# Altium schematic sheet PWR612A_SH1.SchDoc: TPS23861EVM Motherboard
size 558 x 431 mm; Engineer: E. Wright; Revision: A; Name: E. Wright
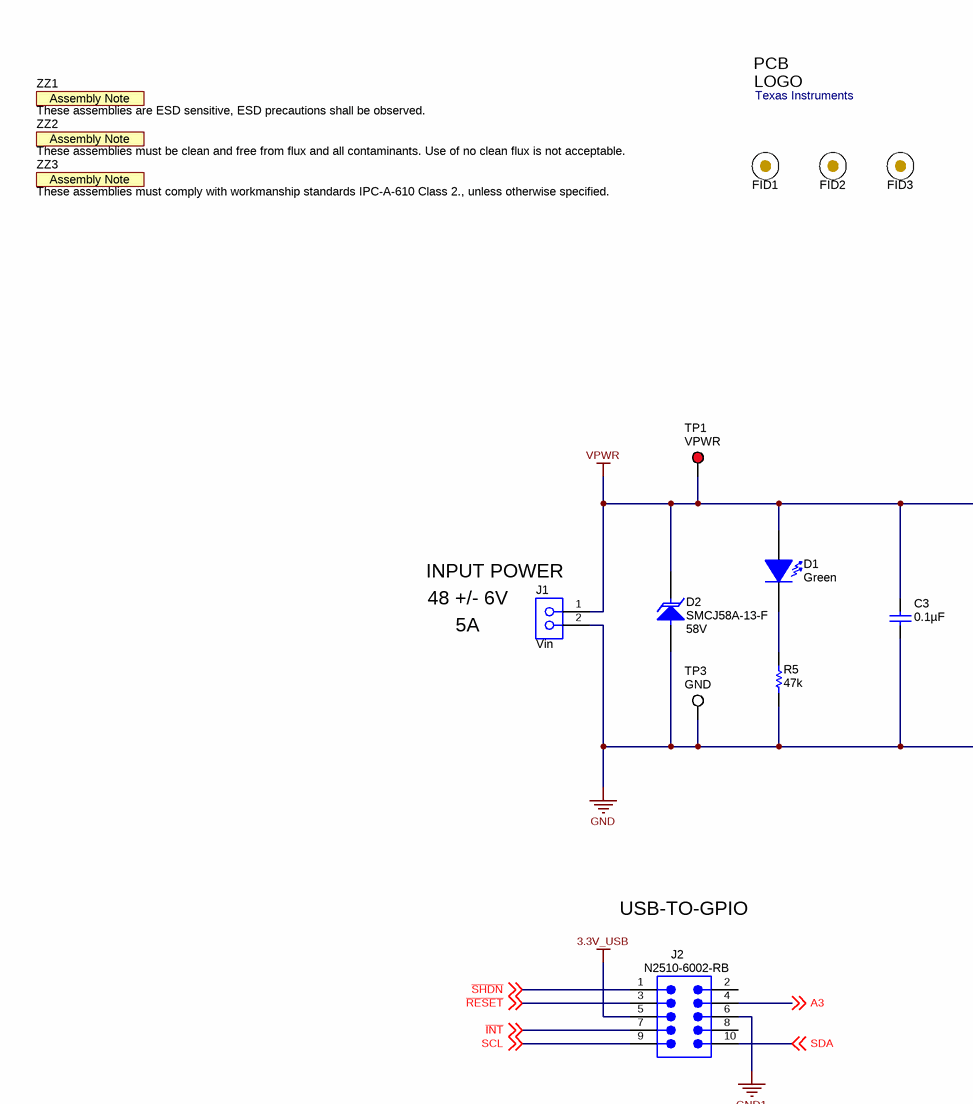
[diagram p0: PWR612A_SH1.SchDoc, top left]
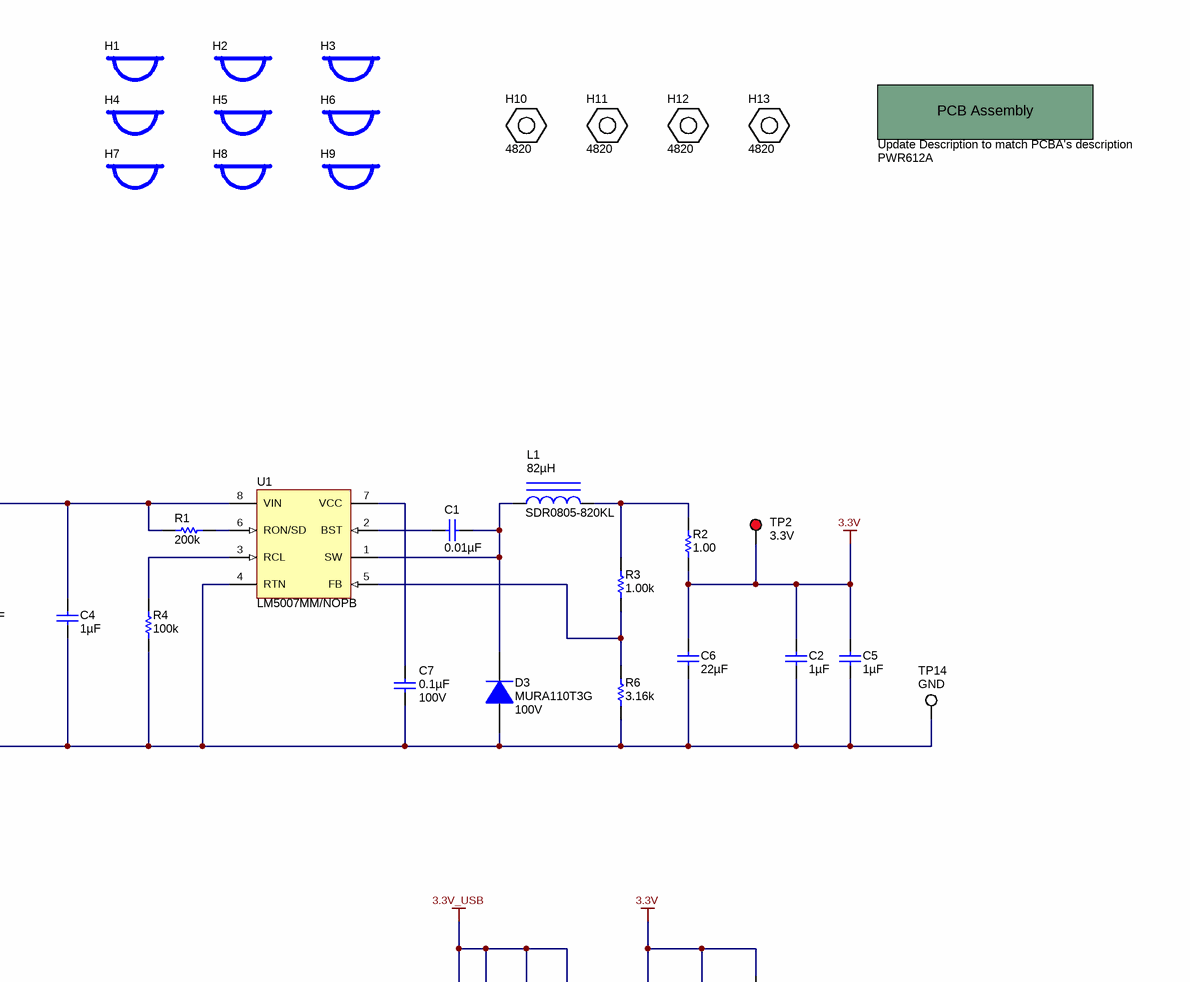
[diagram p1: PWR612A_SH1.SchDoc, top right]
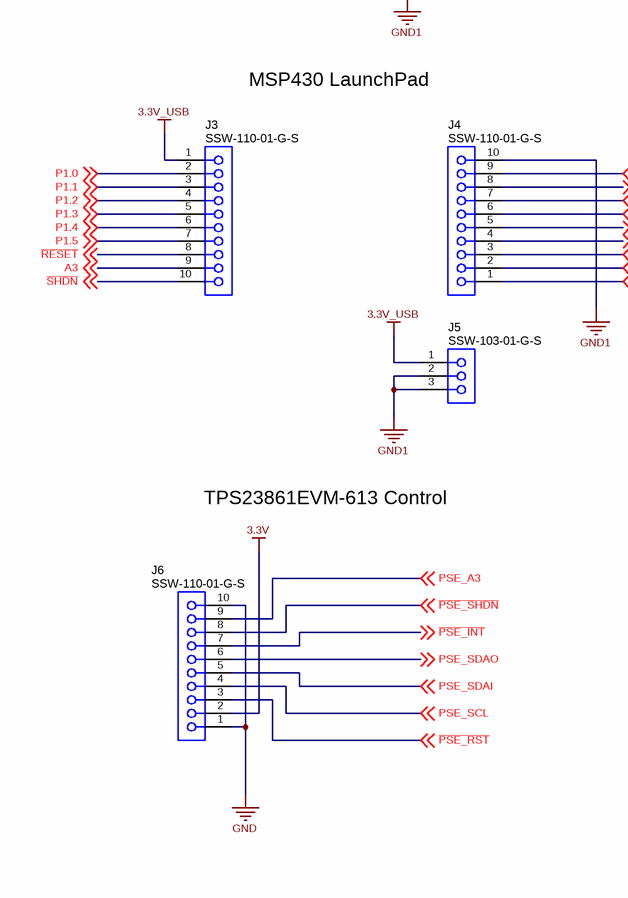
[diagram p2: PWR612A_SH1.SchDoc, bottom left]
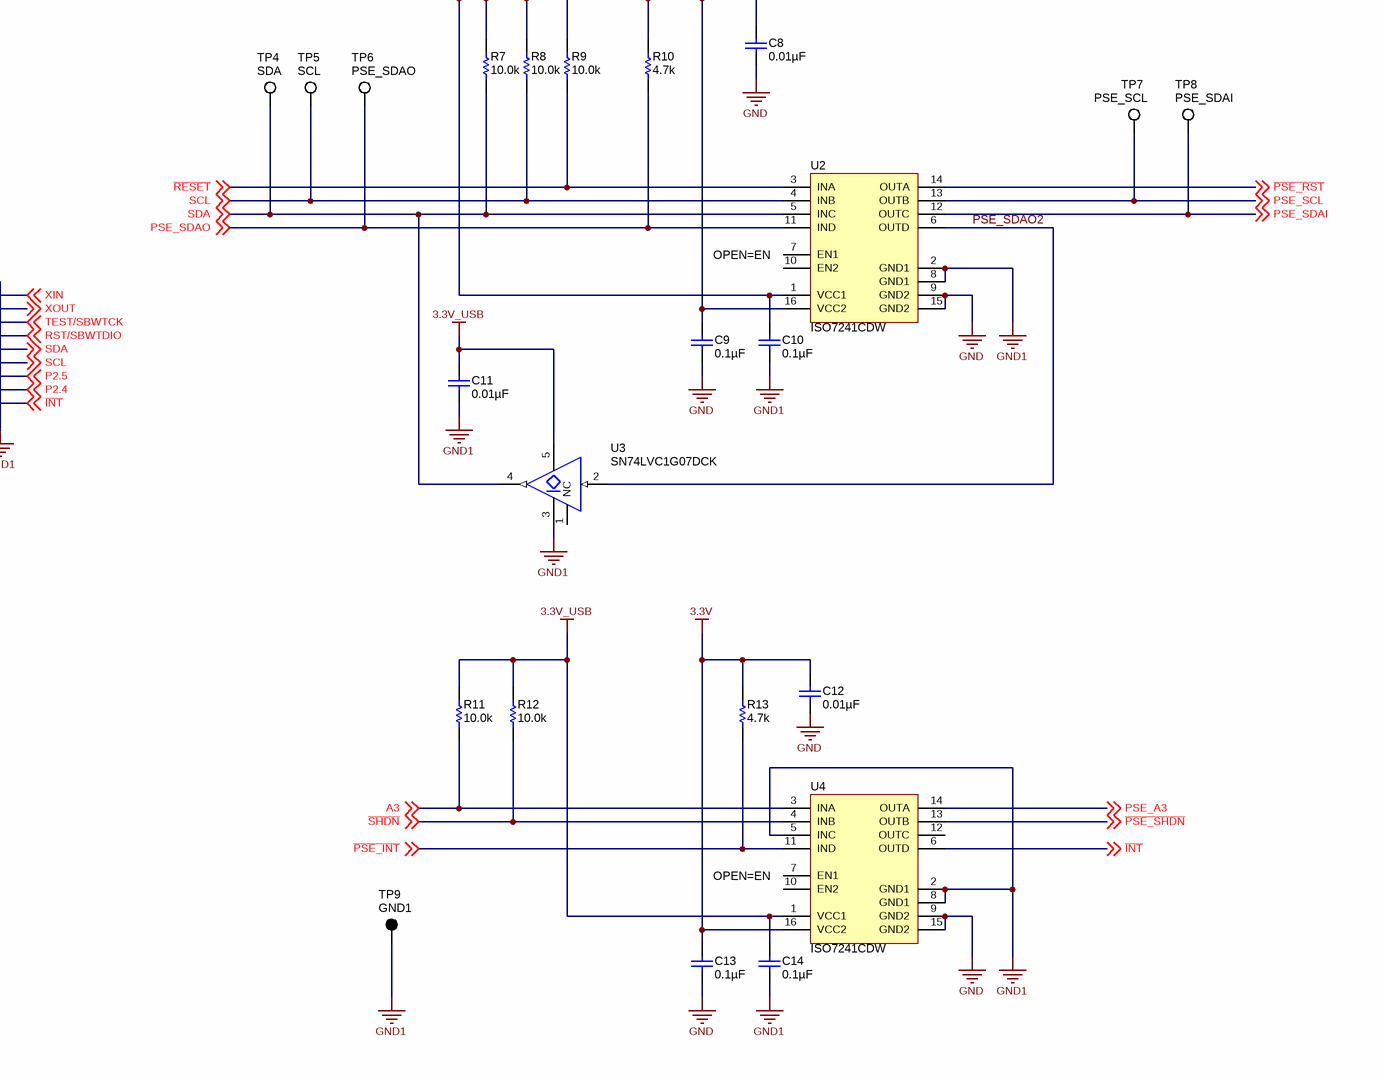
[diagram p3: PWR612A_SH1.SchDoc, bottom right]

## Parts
!PCBA?  Update Description to match PCBA's description  PartNumber: PWR612A  (mechanical)
C1  ValueDisplayed: 0.01µF  [0603]  (hidden comment: 06031C103KAT2A)
C2  ValueDisplayed: 1µF  [0805]  (hidden comment: 0805ZC105KAT2A)
C3  ValueDisplayed: 0.1µF  [0805_HV]  (hidden comment: C2012X7R2A104K)
C4  ValueDisplayed: 1µF  [1206]  (hidden comment: GRM31CR72A105KA01L)
C5  ValueDisplayed: 1µF  [0805]  (hidden comment: 0805ZC105KAT2A)
C6  ValueDisplayed: 22µF  [1206]  (hidden comment: GRM31CR71A226KE15L)
C7  ValueDisplayed: 0.1µF  Value2: 100V  [0805_HV]  (hidden comment: C2012X7R2A104K)
C8  ValueDisplayed: 0.01µF  [0603]  (hidden comment: 06031C103KAT2A)
C9  ValueDisplayed: 0.1µF  [0603]  (hidden comment: 06035C104KAT2A)
C10  ValueDisplayed: 0.1µF  [0603]  (hidden comment: 06035C104KAT2A)
C11  ValueDisplayed: 0.01µF  [0603]  (hidden comment: 06031C103KAT2A)
C12  ValueDisplayed: 0.01µF  [0603]  (hidden comment: 06031C103KAT2A)
C13  ValueDisplayed: 0.1µF  [0603]  (hidden comment: 06035C104KAT2A)
C14  ValueDisplayed: 0.1µF  [0603]  (hidden comment: 06035C104KAT2A)
D1  value Green  [LED_PowerTOPLED_CB_lens]  (hidden comment: LT E63C-CADB-35-L-Z)
D2  SMCJ58A-13-F  value 58V  [SMC]
D3  MURA110T3G  value 100V  [SMA]
FID1  Fiducial  [Fiducial10-20]  (value not drawn)  (no BOM)
FID2  Fiducial  [Fiducial10-20]  (value not drawn)  (no BOM)
FID3  Fiducial  [Fiducial10-20]  (value not drawn)  (no BOM)
H1  SJ61A1  [Bumpon_SJ61A1]  (value not drawn)
H2  SJ61A1  [Bumpon_SJ61A1]  (value not drawn)
H3  SJ61A1  [Bumpon_SJ61A1]  (value not drawn)
H4  SJ61A1  [Bumpon_SJ61A1]  (value not drawn)
H5  SJ61A1  [Bumpon_SJ61A1]  (value not drawn)
H6  SJ61A1  [Bumpon_SJ61A1]  (value not drawn)
H7  SJ61A1  [Bumpon_SJ61A1]  (value not drawn)
H8  SJ61A1  [Bumpon_SJ61A1]  (value not drawn)
H9  SJ61A1  [Bumpon_SJ61A1]  (value not drawn)
H10  4820  [KEYSTONE_4820]
H11  4820  [KEYSTONE_4820]
H12  4820  [KEYSTONE_4820]
H13  4820  [KEYSTONE_4820]
J1  Vin  [CONN_ED120-2DS]
J2  N2510-6002-RB  [CONN_2510-6002]
J3  SSW-110-01-G-S  [CONN_SSW-110-23-F-S]
J4  SSW-110-01-G-S  [CONN_SSW-110-23-F-S]
J5  SSW-103-01-G-S  [CONN_SSW-103-01-G-S]
J6  SSW-110-01-G-S  [CONN_SSW-110-23-F-S]
L1  SDR0805-820KL  ValueDisplayed: 82µH  [SDR0805]
Logo1  Texas Instruments  [TI_Stacked_Overlay_Medium]  (no BOM)
R1  value 200k  [0603]  (hidden comment: CRCW0603200KFKEA)
R2  value 1.00  [1206]  (hidden comment: CRCW12061R00FKEA)
R3  value 1.00k  [0603]  (hidden comment: CRCW06031K00FKEA)
R4  value 100k  [0603]  (hidden comment: CRCW0603100KFKEA)
R5  value 47k  [0603]  (hidden comment: CRCW060347K0JNEA)
R6  value 3.16k  [0603]  (hidden comment: CRCW06033K16FKEA)
R7  value 10.0k  [0603]  (hidden comment: CRCW060310K0FKEA)
R8  value 10.0k  [0603]  (hidden comment: CRCW060310K0FKEA)
R9  value 10.0k  [0603]  (hidden comment: CRCW060310K0FKEA)
R10  value 4.7k  [0603]  (hidden comment: CRCW06034K70JNEA)
R11  value 10.0k  [0603]  (hidden comment: CRCW060310K0FKEA)
R12  value 10.0k  [0603]  (hidden comment: CRCW060310K0FKEA)
R13  value 4.7k  [0603]  (hidden comment: CRCW06034K70JNEA)
TP1  VPWR  [Keystone5010]
TP2  3.3V  [Keystone5010]
TP3  GND  [Testpoint_Keystone_Compact]
TP4  SDA  [Keystone5012]
TP5  SCL  [Keystone5012]
TP6  PSE_SDAO  [Keystone5012]
TP7  PSE_SCL  [Keystone5012]
TP8  PSE_SDAI  [Keystone5012]
TP9  GND1  [Keystone5011]
TP14  GND  [Testpoint_Keystone_Compact]
U1  LM5007MM/NOPB  [MUA08A_N]
U2  ISO7241CDW  [DW0016A_N]
U3  SN74LVC1G07DCK  [DCK0005A_N]
U4  ISO7241CDW  [DW0016A_N]
ZZ1  These assemblies are ESD sensitive, ESD precautions shall be observed.  [AssemblyNote]  (no BOM)
ZZ2  These assemblies must be clean and free from flux and all contaminants. Use of no clean flux is not acceptable.  [AssemblyNote]  (no BOM)
ZZ3  These assemblies must comply with workmanship standards IPC-A-610 Class 2., unless otherwise specified.  [AssemblyNote]  (no BOM)

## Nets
3.3V: C2.1 C5.1 C6.1 C8.2 C9.1 C12.2 C13.1 J6.2 R2.2 R10.2 R13.2 TP2.1 U2.16(VCC2) U4.16(VCC2)
3.3V_USB: C10.1 C11.2 C14.1 J2.5 J3.1 J5.1 R7.2 R8.2 R9.2 R11.2 R12.2 U2.1(VCC1) U3.5(VCC) U4.1(VCC1)
GND: C2.2 C3.2 C4.2 C5.2 C6.2 C7.2 C8.1 C9.2 C12.1 C13.2 D2.2(A) D3.2(A) J1.2 J6.1 J6.10 R4.1 R5.1 R6.1 TP3.1 TP14.1 U1.4(RTN) U2.9(GND2) U2.15(GND2) U4.9(GND2) U4.15(GND2)
GND1: C10.2 C11.1 C14.2 J2.6 J4.10 J5.2 J5.3 TP9.1 U2.2(GND1) U2.8(GND1) U3.3(GND) U4.2(GND1) U4.5(INC) U4.8(GND1)
VPWR: C3.1 C4.1 D1.4(A) D2.1(K) J1.1 R1.1 TP1.1 U1.8(VIN)
~{INT}: J2.7 J4.1 U4.6(OUTD) ; off-sheet ~{INT}
~{PSE_INT}: J6.7 R13.1 U4.11(IND) ; off-sheet ~{PSE_INT}
~{PSE_RST}: J6.3 U2.14(OUTA) ; off-sheet ~{PSE_RST}
~{PSE_SHDN}: J6.8 U4.13(OUTB) ; off-sheet ~{PSE_SHDN}
~{RESET}: J2.3 J3.8 R9.1 U2.3(INA) ; off-sheet ~{RESET}
~{SHDN}: J2.1 J3.10 R12.1 U4.4(INB) ; off-sheet ~{SHDN}
A3: J2.4 J3.9 R11.1 U4.3(INA) ; off-sheet A3
P1.0: J3.2 ; off-sheet P1.0
P1.1: J3.3 ; off-sheet P1.1
P1.2: J3.4 ; off-sheet P1.2
P1.3: J3.5 ; off-sheet P1.3
P1.4: J3.6 ; off-sheet P1.4
P1.5: J3.7 ; off-sheet P1.5
P2.4: J4.2 ; off-sheet P2.4
P2.5: J4.3 ; off-sheet P2.5
PSE_A3: J6.9 U4.14(OUTA) ; off-sheet PSE_A3
PSE_SCL: J6.4 TP7.1 U2.13(OUTB) ; off-sheet PSE_SCL
PSE_SDAI: J6.5 TP8.1 U2.12(OUTC) ; off-sheet PSE_SDAI
PSE_SDAO: J6.6 R10.1 TP6.1 U2.11(IND) ; off-sheet PSE_SDAO
PSE_SDAO2: U2.6(OUTD) U3.2(A)
RST/SBWTDIO: J4.6 ; off-sheet RST/SBWTDIO
SCL: J2.9 J4.4 R8.1 TP5.1 U2.4(INB) ; off-sheet SCL
SDA: J2.10 J4.5 R7.1 TP4.1 U2.5(INC) U3.4(Y) ; off-sheet SDA
TEST/SBWTCK: J4.7 ; off-sheet TEST/SBWTCK
XIN: J4.9 ; off-sheet XIN
XOUT: J4.8 ; off-sheet XOUT
NetC1_1: C1.1 U1.2(BST)
NetC1_2: C1.2 D3.1(K) L1.1 U1.1(SW)
NetC7_1: C7.1 U1.7(VCC)
NetD1_2: D1.2(K) R5.2
NetL1_2: L1.2 R2.1 R3.2
NetR1_2: R1.2 U1.6(RON/SD)
NetR3_1: R3.1 R6.2 U1.5(FB)
NetR4_2: R4.2 U1.3(RCL)

Not connected (* = marked no-connect by the designer): J2 2 8; U2 7(EN1) 10(EN2); U3 1(NC); U4 7(EN1) 10(EN2) 12(OUTC)

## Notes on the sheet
- (near J1) 48 +/- 6V
- (near J1) INPUT POWER
- 5A
- USB-TO-GPIO
- MSP430 LaunchPad
- (near U2) OPEN=EN
- TPS23861EVM-613 Control
- (near U4) OPEN=EN

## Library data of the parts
!PCBA? = PCBA: Manufacturer: Any; SymbolCreator: a0412235; U/M: EA
C1 C8 C11 C12 = 06031C103KAT2A: CAP, CERM, 0.01uF, 100V, +/-10%, X7R, 0603; Manufacturer: AVX; Polarized: N; CompType: Capacitor; U/M: EA; Cap_F: 0.00000001; Tolerance_%: 10; ESR_Ohm: 0.098; Value1: 0.098 ohm; VDC_V: 100; TaMin_C: -55; TaMax_C: 125
C2 C5 = 0805ZC105KAT2A: CAP, CERM, 1uF, 10V, +/-10%, X7R, 0805; Manufacturer: AVX; Polarized: N; CompType: Capacitor; U/M: EA; Cap_F: 0.000001; Tolerance_%: 10; ESR_Ohm: 0.008; Value1: 0.008 ohm; TaMin_C: -55; TaMax_C: 125
C3 C7 = C2012X7R2A104K: CAP, CERM, 0.1uF, 100V, +/-10%, X7R, 0805; Manufacturer: TDK; Polarized: N; CompType: Capacitor; U/M: EA; Cap_F: 0.0000001; Tolerance_%: 10; ESR_Ohm: 0.0158; Value1: 0.0158 ohm; VDC_V: 100; TaMin_C: -55; TaMax_C: 125; Cap_Case: 0805
C4 = GRM31CR72A105KA01L: CAP, CERM, 1uF, 100V, +/-10%, X7R, 1206; Manufacturer: MuRata; Polarized: N; CompType: Capacitor; U/M: EA; Cap_F: 0.000001; Tolerance_%: 10; Value1: Unknown; VDC_V: 100; TaMin_C: -55; TaMax_C: 125; Cap_Case: 2220
C6 = GRM31CR71A226KE15L: CAP, CERM, 22uF, 10V, +/-10%, X7R, 1206; Manufacturer: MuRata; Polarized: N; CompType: Capacitor; U/M: EA; Cap_F: 0.000022; Tolerance_%: 10; Value1: Unknown; TaMin_C: -55; TaMax_C: 125
C9 C10 C13 C14 = 06035C104KAT2A: CAP, CERM, 0.1uF, 50V, +/-10%, X7R, 0603; Manufacturer: AVX; Polarized: N; CompType: Capacitor; U/M: EA; Cap_F: 0.0000001; Tolerance_%: 10; Value1: Unknown; VDC_V: 50; TaMin_C: -55; TaMax_C: 125
D1 = LT E63C-CADB-35-L-Z: LED, Green, SMD; Manufacturer: OSRAM; Type: InGaN; Vf_V: 3.8; Value2: 3.8V; Io_A: 0.03; Vr_V: 5; RJC_CperW: 180; Tjmax_C: 125; Power_TotalModule: 0.114; Value1: 0.114W; LambdaP: 520; LambdaD: 525; NumParallelLEDs: 1; LuminousFlux_PhiV: 1.482; Angle: 20; FamilyName: Power TOPLED&#174;; U/M: EA
D2 = SMBJ58A-13-F: Diode, TVS, Uni, 58V, 600W, SMB; Manufacturer: Diodes Inc.; U/M: EA; Power_W: 5; Vr_V: 58; Value1: 5W
D3 = MURA120T3G: Diode, Ultrafast, 100V, 1A, SMA; Manufacturer: ON Semiconductor; U/M: EA; Vf_V: 0.0875; Value2: 0.0875V; Io_A: 1; Vr_V: 100; TJmax_C: 175
FID1-FID3 = Fiducial: Fiducial mark.  There is nothing to buy or mount.; SymbolCreator: codlsc
H1-H9 = SJ61A1: Bumpon, Cylindrical, 0.312 X 0.200, Black; Manufacturer: 3M; SymbolCreator: a0412235
H10-H13 = 4820: Standoff, Hex, 1"L #6-32 Nylon, M-F; Manufacturer: Keystone; SymbolCreator: a0412235
J1 = ED120/2DS: TERMINAL BLOCK 5.08MM VERT 2POS; Manufacturer: On-Shore Technology, Inc.; U/M: EA
J2 = N2510-6002-RB: Header (shrouded), 100mil, 5x2, High-Temperature, Gold, TH; Manufacturer: 3M; SymbolCreator: a0412235; CompType: Connector; U/M: EA
J3 J4 J6 = SSW-110-23-F-S: Connector, Receptacle, 100mil, 10x1, Gold plated, TH; Manufacturer: Samtec, Inc.; SymbolCreator: a0411947; U/M: EA
J5 = SSW-103-01-G-S: Receptacle 100mil 3x1, Gold, TH; Manufacturer: Samtec, Inc.; SymbolCreator: a0412235; U/M: EA
L1 = SDR0805-820KL: Inductor, Drum Core, Ferrite, 82uH, 0.78A, 0.37 ohm, SMD; Manufacturer: Bourns; Alternate Manufacturer: Wurth Elektronik; Alternate PartNumber: 744787820; Ind_H: 82.0E-6; Imax_A: 0.78; Irms: 0.78A @ 40C rise; Isat: 1.2A @ 10% inductance drop; DCR_ohm: 0.37; U/M: EA
Logo1 = TI_Logo: Texas Instrument Corporate Signature; SymbolCreator: codlsc
R1 = CRCW0603200KFKEA: RES, 200k ohm, 1%, 0.1W, 0603; Manufacturer: Vishay-Dale; CompType: Resistor; Res_ohm: 200000; Tolerance_%: 1; Power_W: 0.1; VDC_V: 75; TempCo: 100 ppm/C; EIA_Code: E96; U/M: EA
R2 = CRCW12061R00FKEA: RES, 1.00 ohm, 1%, 0.25W, 1206; Manufacturer: Vishay-Dale; CompType: Resistor; Res_ohm: 1; Value_Code: 1R00; Power_W: 0.25; VDC_V: 200; TempCo: 100 ppm/C; EIA_Code: E96; U/M: EA
R3 = CRCW06031K00FKEA: RES, 1.00k ohm, 1%, 0.1W, 0603; Manufacturer: Vishay-Dale; CompType: Resistor; Res_ohm: 1000; Value_Code: 1k00; Tolerance_%: 1; Power_W: 0.1; VDC_V: 75; TempCo: 100 ppm/C; EIA_Code: E96; U/M: EA
R4 = CRCW0603100KFKEA: RES, 100k ohm, 1%, 0.1W, 0603; Manufacturer: Vishay-Dale; CompType: Resistor; Res_ohm: 100000; Tolerance_%: 1; Power_W: 0.1; VDC_V: 75; TempCo: 100 ppm/C; EIA_Code: E96; U/M: EA
R5 = CRCW060347K0JNEA: RES, 47k ohm, 5%, 0.1W, 0603; Manufacturer: Vishay-Dale; CompType: Resistor; Res_ohm: 47000; Value_Code: 47k0; Tolerance_%: 5; Power_W: 0.1; VDC_V: 75; TempCo: 200 ppm/C; EIA_Code: E24; U/M: EA
R6 = CRCW06033K16FKEA: RES, 3.16k ohm, 1%, 0.1W, 0603; Manufacturer: Vishay-Dale; CompType: Resistor; Res_ohm: 3160; Value_Code: 3k16; Tolerance_%: 1; Power_W: 0.1; VDC_V: 75; TempCo: 100 ppm/C; EIA_Code: E96; U/M: EA
R7-R9 R11 R12 = CRCW060310K0FKEA: RES, 10.0k ohm, 1%, 0.1W, 0603; Manufacturer: Vishay-Dale; CompType: Resistor; Res_ohm: 10000; Value_Code: 10k0; Tolerance_%: 1; Power_W: 0.1; VDC_V: 75; TempCo: 100 ppm/C; EIA_Code: E96; U/M: EA
R10 R13 = CRCW06034K70JNEA: RES, 4.7k ohm, 5%, 0.1W, 0603; Manufacturer: Vishay-Dale; CompType: Resistor; Res_ohm: 4700; Value_Code: 4k70; Tolerance_%: 5; Power_W: 0.1; VDC_V: 75; TempCo: 200 ppm/C; EIA_Code: E24; U/M: EA
TP1 TP2 = 5010: Test Point, Multipurpose, Red, TH; Manufacturer: Keystone; CompType: Test Point Loop; U/M: EA
TP3 TP14 = 5016: Test Point, Compact, SMT; Manufacturer: Keystone; CompType: Test Point Loop; U/M: EA
TP4-TP8 = 5012: Test Point, Multipurpose, White, TH; Manufacturer: Keystone; CompType: Test Point Loop; U/M: EA
TP9 = 5011: Test Point, Multipurpose, Black, TH; Manufacturer: Keystone; CompType: Test Point Loop; U/M: EA
U1 = LM5007MM/NOPB: High Voltage (80V) Step Down Switching Regulator, 8-pin MSOP, Pb-Free; Manufacturer: National Semiconductor; PackageTopMarking: ZXTT*S81B; PowerWise: N; CompType: Switcher
U2 U4 = ISO7241CDW: 25 Mbps Quad Channels, 3 / 1, Digital Isolator, 3.3 V / 5 V, -40 to +125 degC, 16-pin SOIC (DW), Green (RoHS & no Sb/Br); Manufacturer: Texas Instruments; Alternate Manufacturer: None; Alternate PartNumber: Equivalent; Datarate(Mbps): 25; Eco-Plan: TBD; Input Noise Filter: Yes; Insulation Rating(VRMS): 2500; Prop Delay(Max)(ns): 42; Rating: Catalog; Supply Voltage(s)(V): 3.3, 5; TTL/CMOS Input Threshold: TTL
U3 = SN74LVC1G07DCK: SINGLE BUFFER/DRIVER WITH OPEN-DRAIN OUTPUT, DCK0005A; Alternate Manufacturer: None; Manufacturer: Texas Instruments; SymbolCreator: a0411947; CompType: IC; U/M: EA
ZZ1-ZZ3 = AssemblyNote: SymbolCreator: codlsc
